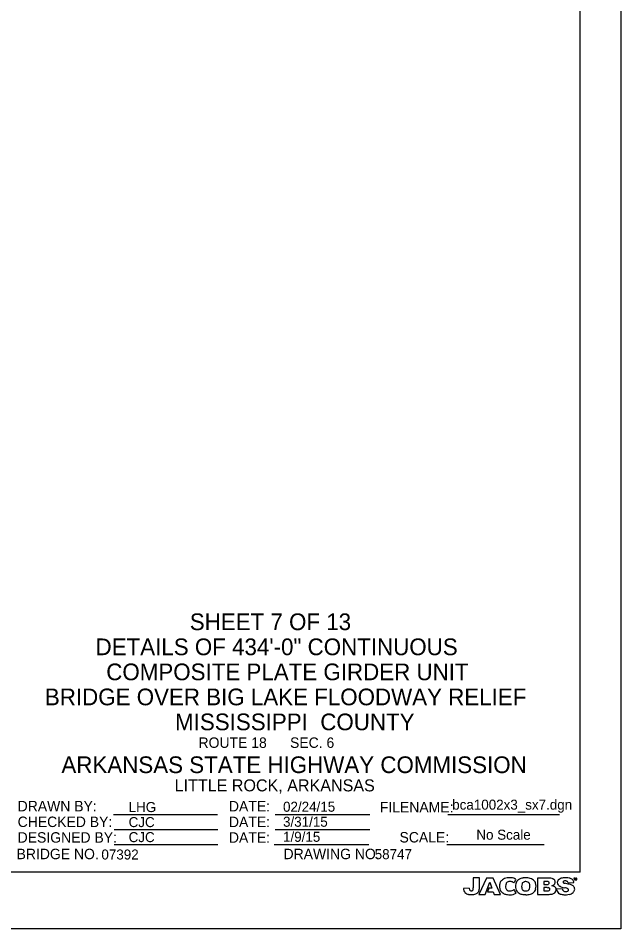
# Model space of a CAD drawing. Extents: x 208.7 to 242.8, y 328.9 to 350.7.
# Drawn here: x 235.56 to 242.78, y 328.91 to 339.81 of the extents above; entities that cross this region are included whole.
import ezdxf

# ---------------------------------------------------------------- set-up
doc = ezdxf.new("R2010")
doc.units = 0
for name, color, linetype in [('border', 7, 'Continuous'), ('Border 2660-Hwy18 - Level 62', 7, 'Continuous'), ('Border 2660-Hwy18 - Text', 7, 'Continuous'), ('Border 2660-Hwy18 - Title Text', 7, 'Continuous'), ('Bridge No BLFR', 7, 'Continuous'), ('Text', 7, 'Continuous'), ('Title Text', 7, 'Continuous')]:
    doc.layers.add(name, color=color, linetype=linetype)

msp = doc.modelspace()

# ---------------------------------------------------------------- linework, layer by layer
at = {"layer": 'border'}
for p, q in [((242.291, 329.584), (242.291, 350.129)), ((236.703, 330.275), (237.947, 330.275)), ((238.637, 330.274), (239.771, 330.274)), ((240.707, 330.274), (242.043, 330.274)), ((236.711, 330.095), (237.954, 330.095)), ((238.637, 330.094), (239.771, 330.094)), ((236.711, 329.915), (237.954, 329.915)), ((238.626, 329.914), (239.76, 329.914)), ((240.694, 329.914), (241.86, 329.914)), ((242.291, 329.584), (210.28, 329.584))]:
    msp.add_line(p, q, dxfattribs=at)
for points in [[(241.086, 329.404), (241.086, 329.515), (241.011, 329.515), (241.011, 329.394)], [(241.208, 329.462), (241.234, 329.391), (241.196, 329.391), (241.18, 329.349), (241.25, 329.349), (241.262, 329.317), (241.339, 329.317), (241.249, 329.513), (241.169, 329.513), (241.079, 329.317), (241.154, 329.317), (241.208, 329.462)], [(241.925, 329.513), (241.782, 329.513), (241.782, 329.317)], [(241.89, 329.473), (241.857, 329.473), (241.857, 329.436)], [(241.857, 329.436), (241.891, 329.436)], [(242.148, 329.454), (242.217, 329.458)], [(242.229, 329.51), (242.214, 329.51), (242.214, 329.508), (242.22, 329.508), (242.22, 329.492), (242.223, 329.492), (242.223, 329.508), (242.229, 329.508), (242.229, 329.51)], [(242.234, 329.507), (242.234, 329.507), (242.24, 329.492), (242.242, 329.492), (242.248, 329.507), (242.248, 329.507), (242.248, 329.492), (242.25, 329.492), (242.25, 329.51), (242.247, 329.51), (242.241, 329.495), (242.235, 329.51), (242.231, 329.51), (242.231, 329.492), (242.234, 329.492), (242.234, 329.507)], [(240.964, 329.393), (240.893, 329.389)], [(241.894, 329.398), (241.857, 329.398), (241.857, 329.359)], [(241.857, 329.359), (241.895, 329.359)], [(242.079, 329.385), (242.008, 329.381)], [(241.782, 329.317), (241.91, 329.317)]]:
    msp.add_lwpolyline(points, dxfattribs=at)
for centre, radius, start, end in [((241.424, 329.42), 0.0987, 155.2444, 178.6811), ((241.408, 329.427), 0.0809, 126.8513, 155.2444), ((241.427, 329.401), 0.114, 94.7853, 126.8513), ((241.502, 329.412), 0.104, 161.2834, 178.6702), ((241.427, 329.438), 0.0243, 134.3139, 161.2834), ((241.449, 329.415), 0.0556, 110.7655, 134.3139), ((241.448, 329.153), 0.363, 86.903, 94.7853), ((241.448, 329.418), 0.0529, 91.5073, 110.7655), ((241.45, 329.355), 0.116, 82.6359, 91.5073), ((241.458, 329.421), 0.0493, 65.5548, 82.6359), ((241.461, 329.403), 0.113, 56.9246, 86.903), ((241.429, 329.358), 0.119, 54.6002, 65.5548), ((241.748, 329.337), 0.276, 144.635, 154.8844), ((241.616, 329.417), 0.1, 148.6249, 181.2859), ((241.595, 329.43), 0.0755, 123.8806, 148.6249), ((241.632, 329.375), 0.142, 111.7104, 123.8806), ((241.62, 329.405), 0.109, 96.5371, 111.7104), ((241.682, 329.414), 0.0917, 160.8611, 181.2981), ((241.622, 329.435), 0.0287, 136.1177, 160.8611), ((241.639, 329.419), 0.0518, 117.7176, 136.1177), ((241.652, 329.133), 0.384, 91.9058, 96.5371), ((241.633, 329.431), 0.0382, 100.2108, 117.7176), ((241.642, 329.381), 0.0895, 90.9675, 100.2108), ((241.646, 329.35), 0.166, 73.4477, 92.4253), ((241.641, 329.408), 0.0622, 67.077, 90.4218), ((241.65, 329.43), 0.0386, 24.6274, 67.077), ((241.634, 329.422), 0.056, 2.7442, 24.6274), ((241.661, 329.402), 0.112, 41.1934, 73.4477), ((241.702, 329.438), 0.0579, 18.6966, 41.1934), ((241.633, 329.414), 0.13, 344.5708, 18.6966), ((241.888, 329.338), 0.135, 86.2098, 89.3498), ((241.891, 329.499), 0.0633, 270.0363, 284.1438), ((241.894, 329.421), 0.0514, 74.8723, 86.2098), ((241.902, 329.452), 0.0196, 40.2425, 74.8723), ((241.902, 329.457), 0.0196, 284.1438, 307.8865), ((241.905, 329.453), 0.0149, 307.8866, 341.4625), ((241.909, 329.458), 0.0108, 21.9604, 40.2425), ((241.901, 329.455), 0.0195, 341.4625, 21.9604), ((241.925, 329.409), 0.104, 72.1885, 90.1477), ((241.938, 329.45), 0.0603, 61.4844, 72.1885), ((241.94, 329.454), 0.0564, 34.7868, 61.4844), ((241.947, 329.469), 0.0471, 296.8412, 329.8182), ((241.96, 329.468), 0.0315, 16.9455, 34.7868), ((241.961, 329.46), 0.0307, 329.8182, 347.0949), ((241.947, 329.464), 0.0455, 347.0949, 16.9455), ((242.065, 329.458), 0.0476, 124.08, 177.6485), ((242.059, 329.458), 0.0416, 177.6485, 218.8535), ((242.096, 329.412), 0.103, 108.2808, 124.08), ((242.089, 329.433), 0.0811, 99.8173, 108.2808), ((242.117, 329.274), 0.242, 93.402, 99.8173), ((242.094, 329.464), 0.00815, 165.3108, 208.2887), ((242.101, 329.462), 0.016, 146.4706, 165.3108), ((242.101, 329.469), 0.0169, 211.7417, 226.6339), ((242.095, 329.466), 0.00877, 130.7855, 146.4706), ((242.106, 329.454), 0.0256, 97.3055, 130.7855), ((242.099, 329.468), 0.0145, 226.6339, 245.1429), ((242.116, 329.504), 0.0549, 245.1429, 260.9806), ((242.117, 329.262), 0.254, 80.6549, 93.402), ((242.112, 329.41), 0.0692, 81.3212, 97.3055), ((242.032, 328.977), 0.479, 77.5139, 80.9806), ((242.117, 329.443), 0.0359, 57.474, 81.3212), ((242.125, 329.457), 0.0202, 37.1977, 57.474), ((241.709, 327.514), 1.977, 76.8035, 77.5139), ((242.113, 329.448), 0.0351, 11.0051, 37.1977), ((242.144, 329.424), 0.0897, 57.5906, 80.6549), ((242.123, 329.281), 0.163, 65.6998, 76.8035), ((242.166, 329.458), 0.0494, 39.0736, 57.5906), ((242.156, 329.451), 0.0612, 6.4385, 39.0736), ((241.015, 329.399), 0.123, 184.5698, 198.1069), ((240.949, 329.377), 0.0527, 198.1069, 225.9799), ((240.967, 329.397), 0.0797, 225.9799, 261.0714), ((241.024, 329.391), 0.0602, 178.2556, 191.4961), ((240.992, 329.384), 0.0277, 191.4961, 218.7511), ((240.984, 329.377), 0.0164, 218.7511, 257.488), ((240.988, 329.395), 0.0345, 257.488, 275.7834), ((240.988, 329.386), 0.0257, 275.7834, 301.6926), ((240.995, 329.375), 0.0122, 301.6926, 325.4171), ((240.982, 329.384), 0.0285, 325.4171, 349.1575), ((240.932, 329.394), 0.0792, 349.1575, 360), ((241.005, 329.409), 0.0931, 279.1616, 305.8646), ((241.025, 329.381), 0.0585, 305.8646, 338.7843), ((241.03, 329.379), 0.0527, 338.7843, 350.0951), ((240.541, 329.464), 0.549, 350.0951, 351.3706), ((240.962, 329.4), 0.124, 351.3706, 1.8291), ((241.478, 329.419), 0.153, 178.6811, 194.3912), ((241.386, 329.395), 0.0582, 194.3912, 214.1799), ((241.443, 329.433), 0.127, 214.1799, 231.6615), ((241.412, 329.394), 0.0765, 231.6616, 258.686), ((241.484, 329.413), 0.0855, 178.6702, 195.8531), ((241.442, 329.401), 0.0421, 195.8531, 214.5369), ((241.44, 329.399), 0.0388, 214.5369, 253.1918), ((241.451, 329.435), 0.0769, 253.1918, 291.1956), ((241.452, 329.459), 0.146, 268.8163, 299.3878), ((241.445, 329.45), 0.0928, 291.1956, 305.5144), ((241.862, 329.557), 0.407, 206.7197, 213.678), ((241.668, 329.418), 0.152, 181.2859, 193.1956), ((241.587, 329.399), 0.0683, 193.1956, 217.7499), ((241.62, 329.425), 0.111, 217.7499, 244.1703), ((241.609, 329.403), 0.0859, 244.1703, 259.4942), ((241.685, 329.415), 0.0951, 181.2981, 197.9492), ((241.623, 329.394), 0.0299, 197.9492, 222.7741), ((241.636, 329.406), 0.0474, 222.7741, 250.1955), ((241.637, 329.409), 0.0507, 250.1955, 269.1264), ((241.639, 329.55), 0.191, 269.1264, 272.0424), ((241.644, 329.41), 0.0512, 272.0424, 299.5401), ((241.652, 329.397), 0.036, 299.5401, 342.4003), ((241.599, 329.413), 0.091, 342.4003, 0.0845), ((241.441, 329.413), 0.249, 0.0845, 2.7442), ((241.667, 329.417), 0.101, 285.9017, 322.6714), ((241.692, 329.398), 0.0698, 322.6714, 344.5708), ((241.89, 329.151), 0.247, 86.6838, 88.8756), ((241.895, 329.463), 0.104, 270.0001, 276.6749), ((241.901, 329.349), 0.0497, 75.9314, 86.6838), ((241.902, 329.402), 0.043, 276.6749, 293.0645), ((241.905, 329.365), 0.0328, 59.6202, 75.9314), ((241.912, 329.379), 0.0178, 293.0645, 337.5037), ((241.914, 329.38), 0.015, 30.8341, 59.6202), ((241.912, 329.379), 0.0177, 337.5037, 30.8341), ((241.934, 329.494), 0.0753, 284.6785, 296.8411), ((241.937, 329.33), 0.092, 61.0815, 79.9242), ((241.946, 329.381), 0.0609, 279.6279, 313.6357), ((241.963, 329.377), 0.039, 44.9773, 61.0815), ((241.953, 329.374), 0.0511, 313.6357, 342.9845), ((241.959, 329.373), 0.0452, 342.9845, 44.9773), ((242.385, 329.434), 0.38, 187.9971, 189.0947), ((242.059, 329.382), 0.0503, 189.0947, 202.464), ((242.094, 329.397), 0.0881, 202.464, 215.8926), ((242.073, 329.381), 0.0621, 215.8926, 243.2968), ((242.071, 329.467), 0.0566, 218.8535, 233.6549), ((242.084, 329.486), 0.0797, 233.6549, 244.7689), ((242.086, 329.407), 0.0904, 243.2968, 257.4598), ((242.117, 329.555), 0.156, 244.7689, 253.473), ((242.164, 329.715), 0.323, 253.473, 259.8297), ((242.13, 329.393), 0.0523, 188.5141, 201.638), ((242.111, 329.385), 0.0319, 201.638, 242.3635), ((242.117, 329.397), 0.045, 242.3635, 264.6229), ((242.055, 329.105), 0.297, 76.0104, 79.8297), ((242.121, 329.432), 0.0806, 264.6229, 273.901), ((242.123, 329.398), 0.0464, 273.901, 289.1925), ((242.103, 329.298), 0.0974, 67.9593, 76.0104), ((242.13, 329.379), 0.0263, 289.1925, 322.566), ((242.13, 329.364), 0.0265, 39.9313, 67.9593), ((242.139, 329.372), 0.0145, 2.1813, 39.9313), ((242.139, 329.372), 0.0141, 322.566, 2.1813), ((242.14, 329.424), 0.109, 282.5001, 295.6144), ((242.153, 329.395), 0.0772, 295.6144, 314.022), ((242.158, 329.358), 0.0776, 51.3565, 65.6998), ((242.174, 329.378), 0.0523, 36.5162, 51.3565), ((242.165, 329.384), 0.0608, 314.022, 345.1611), ((242.177, 329.38), 0.0486, 345.1611, 36.5162), ((240.993, 329.559), 0.244, 261.0714, 269.9405), ((240.993, 329.482), 0.167, 269.9405, 279.1616), ((241.455, 329.611), 0.298, 258.686, 268.8163), ((241.648, 329.613), 0.299, 259.4942, 268.6426), ((241.646, 329.493), 0.18, 268.6426, 285.9017), ((241.9, 329.655), 0.338, 271.7224, 279.6279), ((242.112, 329.526), 0.213, 257.4598, 268.8656), ((242.12, 329.894), 0.581, 268.8656, 270.7612), ((242.125, 329.491), 0.177, 270.7612, 282.5001)]:
    msp.add_arc(centre, radius, start, end, dxfattribs=at)
at = {"layer": 'Border 2660-Hwy18 - Level 62'}
msp.add_lwpolyline([(208.659, 350.715), (242.778, 350.715), (242.778, 328.905), (208.659, 328.905)], close=True, dxfattribs=at)

# ---------------------------------------------------------------- texts
at = {"layer": 'Border 2660-Hwy18 - Text'}
for s, p in [('DRAWN BY:', (235.555, 330.312)), ('DATE:', (238.085, 330.311)), ('FILENAME:', (239.892, 330.299)), ('CHECKED BY:', (235.555, 330.124)), ('DATE:', (238.085, 330.123)), ('DESIGNED BY:', (235.555, 329.937)), ('DATE:', (238.085, 329.936)), ('SCALE:', (240.128, 329.939)), ('BRIDGE NO.', (235.542, 329.739)), ('DRAWING NO.', (238.739, 329.739))]:
    msp.add_text(s, height=0.125, dxfattribs=at).set_placement(p)
at = {"layer": 'Border 2660-Hwy18 - Title Text'}
for s, height, p in [('MISSISSIPPI  COUNTY', 0.2, (237.44, 331.283)), ('ROUTE 18      SEC. 6', 0.125, (237.721, 331.072)), ('ARKANSAS STATE HIGHWAY COMMISSION', 0.2, (236.079, 330.77)), ('LITTLE ROCK, ARKANSAS', 0.144, (237.435, 330.551))]:
    msp.add_text(s, height=height, dxfattribs=at).set_placement(p)
at = {"layer": 'Bridge No BLFR'}
msp.add_text('07392', height=0.12, dxfattribs=at).set_placement((236.558, 329.735))
at = {"layer": 'Text'}
for s, p in [('LHG', (236.884, 330.303)), ('02/24/15', (238.733, 330.307)), ('bca1002x3_sx7.dgn', (240.759, 330.332)), ('CJC', (236.884, 330.123)), ('3/31/15', (238.733, 330.127)), ('No Scale', (241.048, 329.972)), ('CJC', (236.884, 329.943)), ('1/9/15', (238.733, 329.947)), ('58747', (239.831, 329.739))]:
    msp.add_text(s, height=0.12, dxfattribs=at).set_placement(p)
at = {"layer": 'Title Text'}
for s, p in [('SHEET 7 OF 13', (237.616, 332.482)), ('DETAILS OF 434\'-0" CONTINUOUS', (236.488, 332.182)), ('COMPOSITE PLATE GIRDER UNIT', (236.616, 331.882)), ('BRIDGE OVER BIG LAKE FLOODWAY RELIEF', (235.881, 331.582))]:
    msp.add_text(s, height=0.2, dxfattribs=at).set_placement(p)

doc.saveas('drawing.dxf')
